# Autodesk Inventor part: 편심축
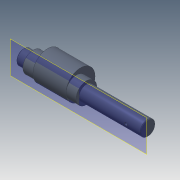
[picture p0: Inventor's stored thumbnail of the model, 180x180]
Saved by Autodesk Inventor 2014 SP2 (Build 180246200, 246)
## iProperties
Manager: 한국ATC센터
Company: 한국ATC센터
Created: 2014-07
Part Number: 편심축
Document SubType Name: Modeling
Designer: KYOUNG IL JANG
Density: 7.86 g/cm^3
Material: 강, 연강
Mass: 1544.74 g
Surface Area: 256.354 cm^2
Volume: 196.531 cm^3
Appearance: 강철
Author: KYOUNG IL JANG
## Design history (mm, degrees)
sketch "스케치1"
  geometry: L1 (-105, 0)-(105, 0); L2 (-105, 0)-(-105, 12.5); L3 (-105, 12.5)-(-89, 12.5); L4 (-89, 12.5)-(-89, 17.5); L5 (-89, 17.5)-(-82, 17.5); L6 (-82, 17.5)-(-82, 12.5); L7 (-82, 12.5)-(-0.35, 12.5); L8 (-0.35, 12.5)-(-0.35, 11.95); L9 (-0.35, 11.95)-(1, 11.95); L10 (1, 11.95)-(1, 12.5); L11 (1, 12.5)-(105, 12.5); L12 (105, 12.5)-(105, 0); L13 (70, 12.5)-(70, 9.1); L14 (70, 9.1)-(95, 9.1); L15 (95, 9.1)-(95, 12.5); L16 (80, -12.5)-(82.5, -12.5); L17 (82.5, -12.5)-(80, -10); L18 (80, -10)-(80, -12.5); L19 (1, 12.5)-(-0.35, 12.5); 2 further points
  constraints: 38 end point, 8 parallel, 5 collinear, 5 perpendicular, 2 point on line, 1 coincident, 1 horizontal, 1 midpoint, 1 vertical
  dimensions: "d0" = 210 distance of L1.start L1.end; "d1" = 25 diameter of L3 L1; "d2" = 35 diameter of L5 L1; "d3" = 16 distance of L2.end L3.end; "d6" = 1.35 distance of L8.end L9.end; "d7" = 23.9 diameter of L9 L1; "d8" = 3.4 distance between parallel lines of L14 L11; "d9" = 10 distance between parallel lines of L15 L12; "d10" = 25 distance of L13.end L14.end; "d11" = 25 diameter of L16 L1 (= d1); "d12" = 25 distance from line of L12 L16.start; "d13" = 45 deg angle of L17 L18; "d14" = 5 diameter of L16.end L18; "d27" = 104 distance between parallel lines of L10 L12; "d35" = 7 distance of L4.end L5.end
revolve "회전1" stored, may be unused: angle "d15" = 90 deg
revolve "회전2" stored, may be unused: angle "d16" = 90 deg
extrude "돌출1" cut sketch "스케치1" stored distance "d17" = 8; taper "d18" = 0 deg
fillet "모깎기1" dims "d19" = 4
node "작업 평면1"
sketch "스케치2"
  geometry: C1 r 12.5 at (0, 0) reference; C2 r 17.5 at (0, 0); C3 r 24.5 at (0, 7); 1 further point
  constraints: 2 centre point, 1 coincident, 1 tangent, 1 vertical alignment
  dimensions: "d32" = 35 diameter of C2; "d33" = 49 diameter of C3 (derived); "d34" = 7 distance of C3.centre point (0, 0)
extrude "돌출2" join sketch "스케치2" distance "d22" = 56; taper "d23" = 0 deg
chamfer "모따기1" distance "d24" = 1; stored, may be unused: second distance "d25" = 2, angle "d26" = 45 deg
feature "면 이동1" dims "d31" = 83
node "작업 평면2"
node "솔리드1"
other parameters: "d36" = -12.5
